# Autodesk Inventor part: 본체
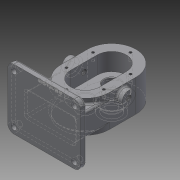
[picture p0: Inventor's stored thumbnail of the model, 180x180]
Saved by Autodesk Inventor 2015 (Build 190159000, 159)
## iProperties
Created: 2020-09
Part Number: 본체
Material: 일반
Document SubType Name: Modeling
Designer: LINEART-SSD.D4.16.06
Density: 1 g/cm^3
Appearance: 기본값
Author: LINEART-SSD.D4.16.06
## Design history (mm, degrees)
sketch "스케치1"
  geometry: L1 (40, 152)-(0, 152); L2 (40, 152)-(80, 152); L3 (40, 90)-(40, 28); L4 (0, 28)-(80, 28); L5 (80, 28)-(80, 152); L6 (80, 152)-(0, 152); L7 (0, 152)-(0, 28); L8 (0, 28)-(80, 152); L9 (80, 28)-(0, 152); 1 further point
  constraints: 18 end point, 3 horizontal, 2 midpoint, 2 parallel, 1 perpendicular
  dimensions: "d7" = 40 distance of L1.start L1.end; "d8" = 40 distance of L1.start L2.end; "d9" = 62 distance of L3.start L3.end
extrude "돌출1" new body sketch "스케치1" distance "d10" = 53; taper "d11" = 0 deg
fillet "모깎기1" dims "d12" = 40
sketch "스케치2"
  geometry: L1 (80, 68)-(80, 112) reference; L2 (0, 112)-(0, 68) reference; L3 (16, 112)-(16, 68); L4 (64, 112)-(64, 68); A1 r 40 centre (40, 68) between (0, 68) and (80, 68) reference; A2 r 40 centre (40, 112) between (80, 112) and (0, 112) reference; A3 r 40 centre (40, 68) between (0, 68) and (80, 68) reference; A4 r 24 centre (40, 112) between (64, 112) and (16, 112); A5 r 24 centre (40, 68) between (16, 68) and (64, 68); 1 further point
  constraints: 4 end point, 4 point on circle, 2 centre point, 2 coincident, 2 tangent
  dimensions: "d40" = 48 diameter of A5
extrude "돌출2" cut sketch "스케치2" distance "d17" = 29; taper "d18" = 0 deg
node "작업 평면1"
sketch "스케치7"
  geometry: L1 (136, 53)-(136, 24) reference; L2 (112, 24)-(136, 24) reference; L3 (124.5, 24)-(124.5, 9); L4 (124.5, 9)-(120.5, 9); L5 (112, 0)-(112, 53) reference; L6 (120.5, 9)-(120.5, -9.7); L7 (120.5, -9.7)-(125.596, -9.7); L8 (112, -25.591)-(112, 0); L9 (126, -17)-(131, -17); L10 (124.5, 24)-(112, 24); L11 (152, 0)-(112, 0) reference; L12 (131, -17)-(131, 0); L13 (131, 0)-(120.5, 0); L14 (112, 24)-(112, 0); L15 (120.5, 0)-(112, 0); L16 (125.596, -9.7)-(126, -10.4); L17 (126, -10.4)-(126, -17); 1 further point
  constraints: 26 end point, 5 perpendicular, 4 point on line, 3 vertical, 1 collinear, 1 horizontal
  dimensions: "d42" = 15 distance between parallel lines of L4 L2; "d43" = 17 distance between parallel lines of L11 L9; "d44" = 7.3 distance between parallel lines of L7 L9; "d48" = 25 diameter of L3 L8; "d49" = 17 diameter of L6 L8; "d51" = 38 diameter of L12 L8; "d120" = 25.59078 distance from line of L8.start L11; "d147" = 0.7 vertical distance of L16.end L7.end; "d148" = 30 deg angle of L17 L16; "d149" = 28 diameter of L17 L8
revolve "회전4" sketch "스케치7" stored, may be unused: angle "d52" = 90 deg
sketch "스케치8"
  geometry: L1 (112, 24)-(136, 24) reference; L2 (120.5, 9)-(120.5, 0); L3 (152, 0)-(112, 0) reference; L4 (112, 24)-(112, 0); L5 (112, 0)-(112, 53) reference; L6 (120.5, 9)-(124.5, 9); L7 (124.5, 9)-(124.5, 24); 1 further point
  constraints: 8 end point, 2 point on line, 1 collinear, 1 horizontal, 1 perpendicular
  dimensions: "d53" = 25 diameter of L7 L4; "d54" = 17 diameter of L2 L4; "d55" = 15 distance between parallel lines of L1 L6
revolve "회전5" sketch "스케치8" stored, may be unused: angle "d56" = 90 deg
sketch "스케치9"
  geometry: L1 (44, 53)-(44, 24) reference; L2 (44, 24)-(68, 24) reference; L3 (56, 24)-(56, 4.58); L4 (68.5, 12.214)-(68.5, 4.58); L5 (68.5, 4.58)-(56, 4.58); L6 (68.5, 12.214)-(68.5, 24); L7 (68.5, 24)-(68, 24); L8 (68, 24)-(112, 24) reference; L9 (68, 24)-(68.5, 24); L10 (68, 24)-(56, 24); 1 further point
  constraints: 14 end point, 3 collinear, 3 vertical, 1 midpoint, 1 perpendicular
  dimensions: "d58" = 25 diameter of L4 L3; "d121" = 19.41962 distance between parallel lines of L8 L5; "d122" = 11.78565 distance from line of L4.start L2
sketch "스케치10"
  geometry: L1 (64, 112)-(64, 68) reference; L2 (16, 68)-(16, 112) reference; C1 r 12.5 at (40, 112) reference; C2 r 12.5 at (40, 112) reference; A1 r 24 centre (40, 68) between (16, 68) and (64, 68) reference; A2 r 24 centre (40, 112) between (64, 112) and (16, 112) reference; A3 r 31 centre (40, 68) between (9, 68) and (71, 68); 6 further points
  constraints: 3 point on circle, 2 coincident, 1 centre point, 1 vertical alignment
  dimensions: "d61" = 31 distance of C1.centre point (40, 143); "d69" = 31 radius of A3
hole "구멍1" sketch "스케치10" at (40, 143), (71, 112), (9, 112), (9, 68), (71, 68), (40, 37) diameter "d62" = 4.134; stored, may be unused: countersink angle "d66" = 90 deg, drill point angle "d68" = 118 deg; dims "d63" = 10, "d64" = 4, "d65" = 2, "d67" = 12
sketch "스케치11"
  geometry: L1 (0, 0)-(-53, 0) reference; L2 (0, 44)-(0, 0) reference; L3 (-53, 44)-(0, 44) reference; L4 (-53, 0)-(-53, 44) reference; L5 (-53, 0)-(0, 0) reference; L6 (0, 44)-(-53, 44) reference; L7 (0, -40)-(-53, -40) reference; C1 r 11 at (-39, 22); 1 further point
  constraints: 1 centre point
  dimensions: "d90" = 14 distance from line of C1.centre L4; "d91" = 22 distance from line of L1 C1.centre; "d92" = 22 diameter of C1
extrude "돌출3" join sketch "스케치11" distance "d72" = 10; taper "d73" = 0 deg
sketch "스케치12"
  geometry: L1 (53, 0)-(0, 0) reference; L2 (53, 44)-(53, 0) reference; L3 (0, 44)-(53, 44) reference; L4 (0, 0)-(0, 44) reference; C1 r 11 at (39, 22); 2 further points
  constraints: 1 centre point, 1 midpoint
  dimensions: "d93" = 14 distance from line of L2 C1.centre; "d94" = 22 distance from line of L1 C1.centre; "d95" = 22 diameter of C1
extrude "돌출4" join sketch "스케치12" distance "d77" = 10; taper "d78" = 0 deg
sketch "스케치16"
  geometry: L1 (68, 53)-(68, 53) reference; L2 (68, 53)-(68, 0) reference; L3 (68, 0)-(68, 0) reference; L4 (68, 0)-(68, 53) reference; L5 (68, 24)-(112, 24) reference; L6 (68, 24)-(80.5, 24); L7 (80.5, 24)-(80.5, 9); L8 (80.5, 9)-(68, 9); L9 (68, 24)-(68, 9); 1 further point
  constraints: 8 end point, 2 point on line, 1 collinear, 1 perpendicular, 1 vertical
  dimensions: "d109" = 15 distance between parallel lines of L5 L8; "d110" = 25 diameter of L7 L2
revolve "회전6" sketch "스케치16" stored, may be unused: angle "d111" = 90 deg
sketch "스케치17"
  geometry: L1 (0, 53)-(-80, 53) reference; L2 (-80, 53)-(-80, 0) reference; L3 (-80, 0)-(0, 0) reference; L4 (0, 0)-(0, 53) reference; L5 (-40, 53)-(-40, -17.335); L6 (-40, -17.335)-(-40, 44.665); L7 (-40, 44.665)-(-40, 82.665); L8 (-40, -17.335)-(20, -17.335); L9 (20, -17.335)-(20, 82.665); L10 (20, 82.665)-(-40, 82.665); L11 (-40, 82.665)-(-100, 82.665); L12 (-100, 82.665)-(-100, -17.335); L13 (-100, -17.335)-(-40, -17.335); 1 further point
  constraints: 18 end point, 2 horizontal, 2 perpendicular, 2 point on line, 1 midpoint, 1 vertical
  dimensions: "d112" = 62 distance of L5.end L6.end; "d113" = 38 distance of L6.end L7.end; "d114" = 60 distance of L5.end L8.end; "d115" = 100 distance of L8.end L9.end; "d116" = 60 distance of L7.end L11.end; "d117" = 100 distance of L11.end L12.end; "d123" = 17.33463 distance between parallel lines of L3 L8
extrude "돌출7" join sketch "스케치17" distance "d118" = 10; taper "d119" = 0 deg
fillet "모깎기3" dims "d124" = 3, "d125" = 10
sketch "스케치18"
  geometry: L1 (97, 7.335)-(97, -72.665) reference; L2 (-10, 14.335)-(90, 14.335) reference; L3 (-17, -72.665)-(-17, 7.335) reference; L4 (90, -79.665)-(-10, -79.665) reference; C1 r 4.5 at (-10, -72.665); C2 r 4.5 at (-10, 7.335); C3 r 4.5 at (90, -72.665); C4 r 4.5 at (90, 7.335); A1 r 7 centre (-10, -72.665) between (-17, -72.665) and (-10, -79.665) reference; A2 r 7 centre (90, -72.665) between (90, -79.665) and (97, -72.665) reference; A3 r 7 centre (90, 7.335) between (97, 7.335) and (90, 14.335) reference; A4 r 7 centre (-10, 7.335) between (-10, 14.335) and (-17, 7.335) reference; A5 r 7 centre (-10, -72.665) between (-17, -72.665) and (-10, -79.665) reference; 1 further point
  constraints: 4 centre point, 4 coincident
  dimensions: "d126" = 9 diameter of C1; "d127" = 9 diameter of C2; "d128" = 9 diameter of C3; "d129" = 9 diameter of C4
extrude "돌출8" cut sketch "스케치18" distance "d130" = 10; taper "d131" = 0 deg
node "작업 평면2"
sketch "스케치19"
  geometry: L1 (0, 10)-(100, 10) reference; L2 (100, 0)-(0, 0) reference; L3 (50, 0)-(10, 0); L4 (50, 0)-(90, 0); L5 (90, 0)-(90, 68); L6 (10, 68)-(10, 0); A1 r 40 centre (50, 68) between (10, 68) and (90, 68) reference; A2 r 40 centre (50, 68) between (10, 68) and (90, 68)
  constraints: 8 end point, 2 point on circle, 1 centre point, 1 coincident, 1 collinear, 1 midpoint, 1 perpendicular, 1 point on line, 1 tangent
  dimensions: "d133" = 40 distance of L3.start L3.end; "d134" = 40 distance of L3.start L4.end (derived)
extrude "돌출9" join sketch "스케치19" distance "d135" = 37; taper "d136" = 0 deg
sketch "스케치20"
  geometry: C1 r 11 at (0, 0) reference; 2 further points
  constraints: 1 coincident
hole "구멍3" sketch "스케치20" at (0, 0) diameter "d137" = 8.376; stored, may be unused: countersink angle "d141" = 90 deg, drill point angle "d143" = 118 deg; dims "d138" = 20, "d139" = 4, "d140" = 2, "d142" = 27.3
fillet "모깎기4" dims "d144" = 3
fillet "모깎기5" dims "d145" = 3
fillet "모깎기6" dims "d146" = 3
chamfer "모따기1" distance "d150" = 1; stored, may be unused: second distance "d151" = 2, angle "d152" = 45 deg
sketch "스케치21"
  geometry: L1 (-10, -82.665)-(90, -82.665) reference; L2 (-20, 7.335)-(-20, -72.665) reference; 2 further points
  constraints: 1 other
  dimensions: "d153" = 12 distance from line of L1 point (40, -70.665); "d154" = 60 distance from line of L2 point (40, -70.665)
feature "엠보싱1" sketch "스케치21" dims "d7" = 40, "d8" = 40, "d9" = 62, "d155" = 0.5, "d156" = 0
node "솔리드1"
node "투영된 루프1"
node "투영된 루프3"
node "투영된 루프4"
node "투영된 루프5"
node "투영된 루프9"
node "투영된 루프10"
node "투영된 루프11"
node "투영된 루프12"
other parameters: "d132" = -25
